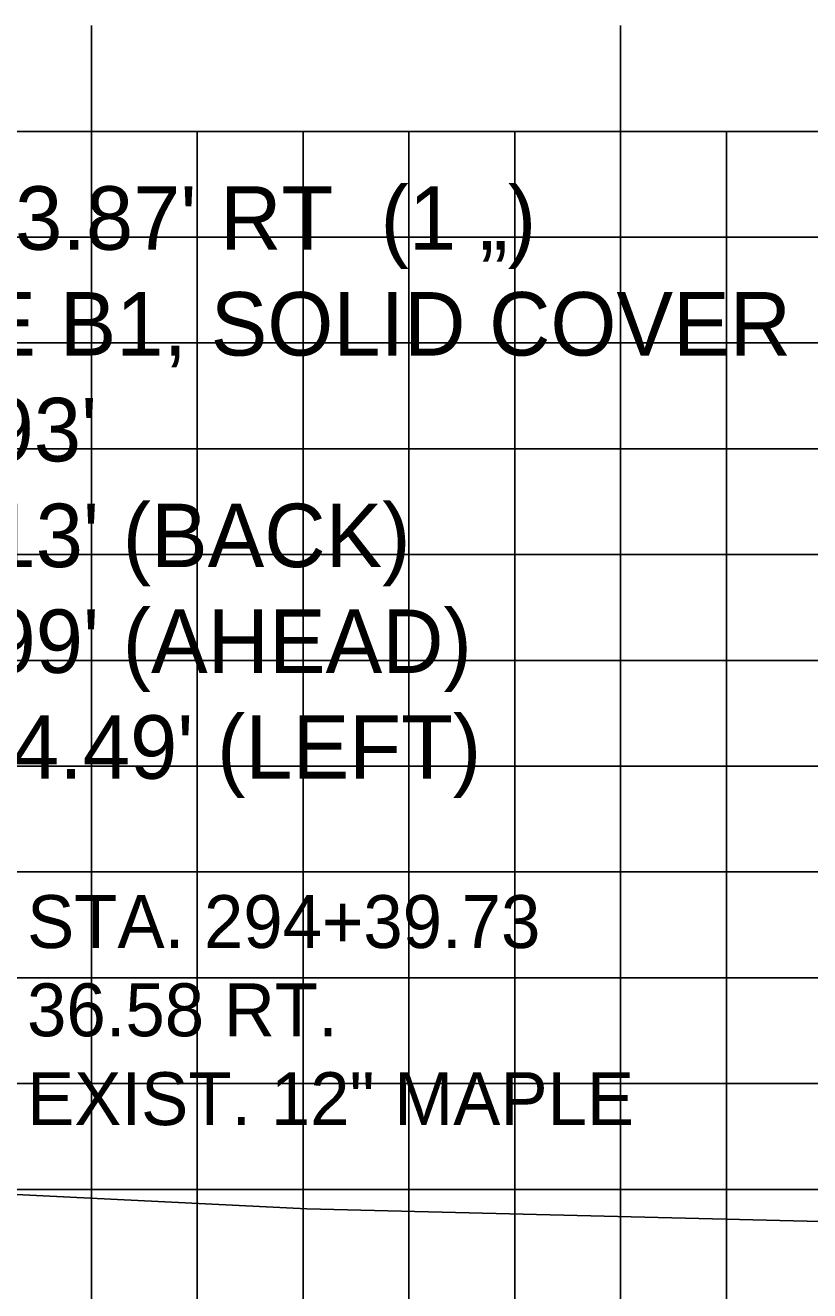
# Model space of a CAD drawing. Extents: x 859352 to 859522, y 366268 to 366378.
# Drawn here: x 859474.5 to 859481.92, y 366286.28 to 366298.24 of the extents above; entities that cross this region are included whole.
import ezdxf

# ---------------------------------------------------------------- set-up
doc = ezdxf.new("R2010")
doc.units = 0
for name, color, linetype in [('D_Drainage_Text', 7, 'Continuous'), ('D_Text_Monospaced', 7, 'Continuous'), ('MAJOR', 7, 'Continuous'), ('MINOR', 7, 'Continuous'), ('S_Roadway_Centerline', 7, 'Continuous')]:
    doc.layers.add(name, color=color, linetype=linetype)

msp = doc.modelspace()

# ---------------------------------------------------------------- linework, layer by layer
at = {"layer": 'MAJOR'}
for p, q in [((859475.129, 366298.238), (859475.129, 366297.236)), ((859480.129, 366298.238), (859480.129, 366297.236)), ((859365.129, 366297.236), (859505.129, 366297.236)), ((859365.129, 366297.236), (859505.129, 366297.236)), ((859475.129, 366277.236), (859475.129, 366297.236)), ((859480.129, 366277.236), (859480.129, 366297.236)), ((859365.129, 366292.236), (859505.129, 366292.236)), ((859365.129, 366287.236), (859505.129, 366287.236))]:
    msp.add_line(p, q, dxfattribs=at)
at = {"layer": 'MINOR'}
for p, q in [((859476.129, 366277.236), (859476.129, 366297.236)), ((859477.129, 366277.236), (859477.129, 366297.236)), ((859478.129, 366277.236), (859478.129, 366297.236)), ((859479.129, 366277.236), (859479.129, 366297.236)), ((859481.129, 366277.236), (859481.129, 366297.236)), ((859365.129, 366296.236), (859505.129, 366296.236)), ((859365.129, 366295.236), (859505.129, 366295.236)), ((859365.129, 366294.236), (859505.129, 366294.236)), ((859365.129, 366293.236), (859505.129, 366293.236)), ((859365.129, 366291.236), (859505.129, 366291.236)), ((859365.129, 366290.236), (859505.129, 366290.236)), ((859365.129, 366289.236), (859505.129, 366289.236)), ((859365.129, 366288.236), (859505.129, 366288.236))]:
    msp.add_line(p, q, dxfattribs=at)
at = {"layer": 'S_Roadway_Centerline'}
msp.add_lwpolyline([(859463.938, 366287.704), (859477.165, 366287.052), (859487.767, 366286.791)], dxfattribs=at)

# ---------------------------------------------------------------- texts
at = {"layer": 'D_Drainage_Text'}
for s, p in [("STA. 294+55.00, 13.87' RT  (1 „)", (859467.694, 366296.117)), ('INSTALL CB TYPE B1, SOLID COVER', (859467.694, 366295.117)), ("RIM ELEV. = 250.93'", (859467.694, 366294.117)), ('12" INV. IN = 245.13\' (BACK)', (859467.694, 366293.117)), ('12" INV. IN = 244.99\' (AHEAD)', (859467.694, 366292.117)), ('18" INV. OUT = 244.49\' (LEFT)', (859467.694, 366291.117))]:
    msp.add_text(s, height=0.6, dxfattribs=at).set_placement(p)
at = {"layer": 'D_Text_Monospaced'}
for s, height, p in [('STA. 294+39.73', 0.49998, (859474.52, 366289.517)), ('36.58 RT.', 0.5, (859474.52, 366288.683)), ('EXIST. 12" MAPLE', 0.49998, (859474.52, 366287.843))]:
    msp.add_text(s, height=height, dxfattribs=at).set_placement(p)

doc.saveas('drawing.dxf')
